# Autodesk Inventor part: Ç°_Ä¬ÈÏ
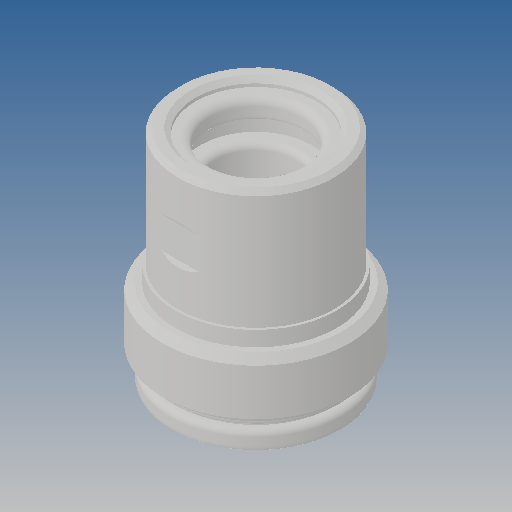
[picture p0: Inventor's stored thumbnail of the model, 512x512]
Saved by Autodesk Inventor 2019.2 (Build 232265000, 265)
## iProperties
Created: 2011-12
Part Number: Ç°_Ä¬ÈÏ
Material: Ogólny
Document SubType Name: Modeling
Designer: CADENGINEERING4
Density: 1 g/cm^3
Appearance: Domyślna
Author: CADENGINEERING4
Revision Number: ÈÎºÎ
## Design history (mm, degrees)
feature "NONE"
node "Bryła1"
